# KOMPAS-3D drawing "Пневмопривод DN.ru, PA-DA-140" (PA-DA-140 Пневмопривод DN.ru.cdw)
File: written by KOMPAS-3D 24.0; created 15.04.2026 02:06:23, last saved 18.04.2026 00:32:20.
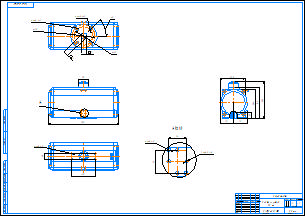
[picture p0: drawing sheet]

Document properties: Автор: DN.ru; Форматы листов документа: A1; Полное имя файла: PA-DA-140 Пневмопривод DN.ru.m3d; Масса: 13; Наименование: Пневмопривод DN.ru; Количество листов документа: 1; Примечание: D290-00298

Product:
- Part/product: Пневмопривод DN.ru  | designation PA-DA-140
    Масса: 13
    Раздел спецификации: Прочие изделия
    Примечание: D290-00298

Views: Вид 1, Вид:1, Проекционный вид 2, Выносной элемент 6, Выносной элемент А, Выносной элемент
Referenced files in C:\Работа\PA-DA-х Пневмопривод DN.ru\052\: PA-DA-052 Пневмопривод DN.ru.m3d
Referenced files in C:\Работа\PA-DA-х Пневмопривод DN.ru\140\: PA-DA-140 Пневмопривод DN.ru.m3d
Referenced files in C:\Program Files\ASCON\KOMPAS-3D v24\Templates\: Чертеж_DN.ru.cdt
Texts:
  objid
  viewid
  PA-DA-140
  Чертеж_DN.ru.cdt
  Пневмопривод
  Пневмопривод DN.ru
  PA-DA-140 Пневмопривод DN.ru
Dimensions and other numbers on the sheet: 0; 3; 2; 4; 55; 608; 390; 9; 4 отв.; 10; 27; 102; 125; 12; 7; 1; 2 отв.; 24; 32; 5; 1:2; 13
